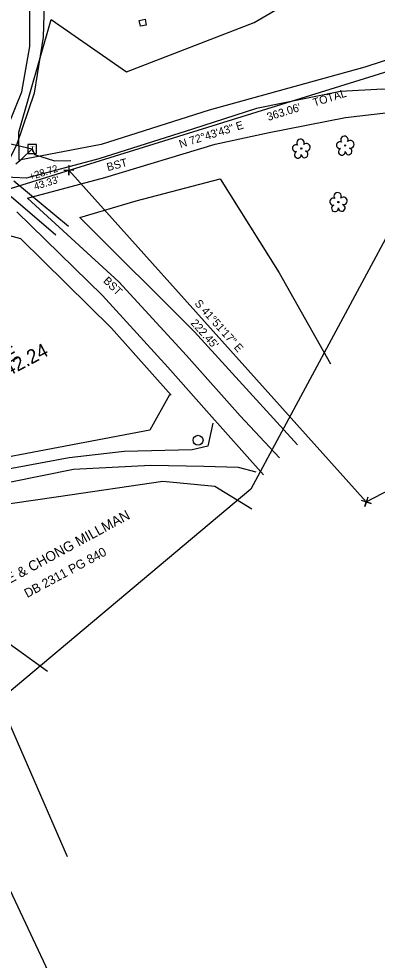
# Model space of a CAD drawing. Extents: x 1380524 to 1382335, y 594765 to 596944.
# Drawn here: x 1381895.1 to 1382074, y 595253.4 to 595723.8 of the extents above; entities that cross this region are included whole.
import ezdxf

# ---------------------------------------------------------------- set-up
doc = ezdxf.new("R2010")
doc.units = 0
for name, color, linetype in [('DTM Contours Major Text', 7, 'Continuous'), ('Exist Horizontal Baseline Alignment Direction Label', 7, 'Continuous'), ('Exist Other Culture Fence Line Text', 7, 'Continuous'), ('Exist Other Culture Well CELL', 7, 'Continuous'), ('Exist Property Tie Line Text', 7, 'Continuous'), ('Exist Right of Way Line', 7, 'Continuous'), ('Exist Roads EOP', 7, 'Continuous'), ('Exist Roads EOP Other', 7, 'Continuous'), ('Exist Structure Major Bridge WW', 7, 'Continuous'), ('Exist Structure Minor Pipes CMP 18 Inch', 7, 'Continuous'), ('Exist Utilities Gas UG Line', 7, 'Continuous'), ('Exist Utilities Power Tower Text', 7, 'Continuous'), ('Exist Utilities Telephone Pedestal CELL', 7, 'Continuous'), ('Exist Utilities Telephone UG Cable', 7, 'Continuous'), ('Prop Drainage Structure Box Number Symbol CELL', 7, 'Continuous'), ('Prop Drainage Structure Pipe Elbow CELL', 7, 'Continuous'), ('Prop Earthen Structure Cut Ditch Special Detail Label', 7, 'Continuous'), ('Prop Erosion Rip Rap At Embankment Detail CELL', 7, 'Continuous'), ('Prop Horizontal Alignment Tick Large', 7, 'Continuous'), ('Scratch_Level_6', 7, 'Continuous')]:
    doc.layers.add(name, color=color, linetype=linetype)

# ---------------------------------------------------------------- blocks, each defined once
blk = doc.blocks.new('EXIST UTILITIES OTHER POLE')
at = {"layer": 'DTM Contours Major Text'}
blk.add_circle((0, 0), 0.0493, dxfattribs=at)
blk = doc.blocks.new('EXIST VEGETATION TREE')
at = {"layer": 'Prop Erosion Rip Rap At Embankment Detail CELL'}
blk.add_line((0, 0), (0, 0), dxfattribs=at)
blk.add_circle((0, 0), 0.00652, dxfattribs=at)
for centre, radius, start, end in [((-0.0077, 0.0575), 0.0371, 330.16508, 219.71335), ((-0.0521, 0.0031), 0.0345, 62.66361, 279.3457), ((0.051, 0.0118), 0.038, 257.1011, 134.19993), ((-0.0341, -0.0624), 0.0338, 111.56708, 6.23104), ((0.0335, -0.058), 0.034, 181.28216, 74.55999)]:
    blk.add_arc(centre, radius, start, end, dxfattribs=at)
blk = doc.blocks.new('EXIST UTILITIES TELEPHONE PEDESTAL')
at = {"layer": 'Exist Utilities Telephone Pedestal CELL'}
blk.add_line((0, 0), (0, 0), dxfattribs=at)
blk.add_lwpolyline([(-0.054, -0.057), (0.057, -0.057), (0.057, 0.055), (-0.054, 0.055), (-0.054, -0.057)], dxfattribs=at)
blk.add_text('T', height=0.0684, dxfattribs=at).set_placement((-0.023, -0.034))

msp = doc.modelspace()

# ---------------------------------------------------------------- linework, layer by layer
at = {"layer": 'Exist Other Culture Well CELL'}
msp.add_lwpolyline([(1381955.16, 595723.01), (1381958.1, 595723.59), (1381958.66, 595720.69), (1381955.73, 595720.12)], close=True, dxfattribs=at)
at = {"layer": 'Exist Roads EOP'}
msp.add_line((1381919.44, 595305.02), (1381827.47, 595515.95), dxfattribs=at)
msp.add_lwpolyline([(1381895.92, 595822.17), (1381902.47, 595793.76), (1381906.2, 595769.7), (1381907.97, 595742.61), (1381907.23, 595714.6), (1381902.73, 595686.65), (1381893.97, 595660.65), (1381884.45, 595642.32), (1381871.1, 595622.85), (1381855.36, 595606.07), (1381838.64, 595592.06), (1381819.68, 595578.62), (1381797.68, 595564.39), (1381777.69, 595551.91), (1381745.42, 595532.92), (1381704.18, 595509.33)], dxfattribs=at)
at = {"layer": 'Exist Roads EOP Other'}
for points in [[(1382105.64, 595686.55), (1382076.86, 595688.73), (1382055.65, 595687.52), (1382013.67, 595678.93), (1381981.76, 595668.62), (1381934.99, 595653.84), (1381898.93, 595644.26), (1381885.04, 595644.78), (1381879.57, 595650.76), (1381878.26, 595659.39)], [(1381899.37, 595634.27), (1381938.06, 595644.53), (1381993.1, 595661.21), (1382020.12, 595666.97), (1382058.22, 595674.5), (1382079.57, 595676.98), (1382102.22, 595669.97)], [(1381899.37, 595634.27), (1381945, 595592.33), (1381978.83, 595555.55), (1382005.63, 595525.4), (1382025.28, 595504.38)], [(1382017.25, 595495.9), (1381988.8, 595527.93), (1381969.42, 595549.67), (1381936.78, 595585.55), (1381894.12, 595627.41)]]:
    msp.add_lwpolyline(points, dxfattribs=at)
at = {"layer": 'Exist Structure Major Bridge WW'}
for p, q in [((1381920.1, 595648.12), (1381920.1, 595648.12)), ((1382068.52, 595482.43), (1382068.52, 595482.43))]:
    msp.add_line(p, q, dxfattribs=at)
for points in [[(1381922.59, 595647.98), (1381917.6, 595648.26), (1381920.1, 595648.12), (1381919.96, 595645.62), (1381920.23, 595650.62)], [(1382069.26, 595484.82), (1382067.79, 595480.04), (1382068.52, 595482.43), (1382070.91, 595481.69), (1382066.13, 595483.17)]]:
    msp.add_lwpolyline(points, dxfattribs=at)
at = {"layer": 'Exist Utilities Gas UG Line'}
msp.add_lwpolyline([(1381819.69, 595439.52), (1382072.96, 594899.37)], dxfattribs=at)
at = {"layer": 'Exist Utilities Power Tower Text'}
for p, q in [((1381879.85, 595635.61), (1382234.24, 595745.79)), ((1381920.1, 595648.12), (1382068.52, 595482.43)), ((1382068.52, 595482.43), (1382333.18, 595622.39))]:
    msp.add_line(p, q, dxfattribs=at)
at = {"layer": 'Exist Utilities Telephone UG Cable'}
for p, q in [((1381900.56, 595709.92), (1381900.64, 595734.04)), ((1381896.64, 595687.3), (1381900.56, 595709.92)), ((1381889.95, 595670.78), (1381896.64, 595687.3)), ((1381888.87, 595661.8), (1381901.65, 595658.8)), ((1381896.49, 595653.89), (1381901.65, 595658.8)), ((1381901.65, 595658.8), (1381902.97, 595656.05)), ((1381902.97, 595656.05), (1381912.82, 595652.88)), ((1381893.52, 595651.3), (1381896.49, 595653.89)), ((1381912.82, 595652.88), (1381920.95, 595652.99)), ((1381919.85, 595620.12), (1381892.51, 595642.73)), ((1381913.61, 595615.68), (1381891.2, 595634.87))]:
    msp.add_line(p, q, dxfattribs=at)
at = {"layer": 'Prop Drainage Structure Box Number Symbol CELL'}
msp.add_lwpolyline([(1382083.62, 595964.41), (1382120.69, 595773.82), (1382095.82, 595646.75), (1382010.85, 595488.75), (1381848.52, 595352.32), (1381617.36, 595239.15), (1381304.92, 595184.07), (1381005.77, 595330.75), (1380937.13, 595525.19), (1380768.47, 595849.39), (1380967, 596250.36)], close=True, dxfattribs=at)
at = {"layer": 'Prop Drainage Structure Pipe Elbow CELL'}
for points in [[(1381991.91, 595521.81), (1381989.38, 595510.26), (1381981.68, 595508.51), (1381947.69, 595507.62), (1381920.27, 595504.37), (1381825.14, 595486.78)], [(1381825.94, 595480.83), (1381875.26, 595489.35), (1381922.43, 595498.8), (1381960.89, 595500.83), (1381987.45, 595500.26), (1382004.5, 595499.71), (1382013.34, 595497.39)]]:
    msp.add_lwpolyline(points, dxfattribs=at)
at = {"layer": 'Prop Earthen Structure Cut Ditch Special Detail Label'}
for points in [[(1382110.04, 595713.45), (1382067.83, 595699.67), (1381990.15, 595678.17), (1381936.17, 595661.06), (1381895.27, 595653.13), (1381895.13, 595667.26), (1381911.22, 595723.52), (1381948.84, 595697.3), (1382012.6, 595721.97), (1382044.15, 595740.68), (1382086.44, 595744.88), (1382118.43, 595781.95)], [(1382034.12, 595510.96), (1381982.79, 595567.38), (1381925.52, 595624.53), (1381953.7, 595632.8), (1381995.62, 595643.94), (1382025.13, 595596.91), (1382050.76, 595551.48)], [(1381970.28, 595535.93), (1381960.54, 595518.19), (1381827.03, 595492.89), (1381805.59, 595553.01), (1381851.27, 595592.48), (1381878.01, 595618.84), (1381895.83, 595614.04), (1381941.37, 595569.31), (1381971.15, 595535.75)], [(1381909.46, 595397.71), (1381844.05, 595444.77), (1381830.9, 595473.02), (1381914.86, 595485.13), (1381966.96, 595492.75), (1381992.9, 595490.3), (1382011.42, 595478.91)]]:
    msp.add_lwpolyline(points, dxfattribs=at)

# ---------------------------------------------------------------- block references
at = {"layer": 'DTM Contours Major Text', "xscale": 50, "yscale": 50}
msp.add_blockref('EXIST UTILITIES OTHER POLE', (1381984.56, 595513.23), dxfattribs=at)
at = {"layer": 'Exist Utilities Telephone Pedestal CELL', "xscale": 40, "yscale": 40}
msp.add_blockref('EXIST UTILITIES TELEPHONE PEDESTAL', (1381901.65, 595658.8), dxfattribs=at)
at = {"layer": 'Prop Erosion Rip Rap At Embankment Detail CELL', "xscale": 50, "yscale": 50}
for p in [(1382036.07, 595659.03), (1382058, 595660.51), (1382054.62, 595632.26)]:
    msp.add_blockref('EXIST VEGETATION TREE', p, dxfattribs=at)

# ---------------------------------------------------------------- texts
at = {"layer": 'Exist Horizontal Baseline Alignment Direction Label'}
msp.add_text('N 61%%d 18\' 37.4" E', height=7, rotation=28.6896, dxfattribs=at).set_placement((1381832.94, 595520.43))
at = {"layer": 'Exist Other Culture Fence Line Text'}
for s, rotation, p in [(' TOTAL', 17.2715, (1382041.18, 595679.48)), ("363.06'", 17.2715, (1382019.65, 595672.79)), ('N 72%%D43\'43" E', 17.2715, (1381975.79, 595659.21)), ('S 41%%D51\'17" E', 311.8548, (1381982.55, 595581.4)), ("222.45'", 311.8548, (1381980.62, 595571.57))]:
    msp.add_text(s, height=4, rotation=rotation, dxfattribs=at).set_placement(p)
at = {"layer": 'Exist Property Tie Line Text'}
for s, p in [('+28.72', (1381900.75, 595643.13)), ("43.33'", (1381903.19, 595638.23))]:
    msp.add_text(s, height=3.6, rotation=17.2715, dxfattribs=at).set_placement(p)
at = {"layer": 'Exist Right of Way Line'}
msp.add_text('CLYDE & CHONG MILLMAN', height=5, rotation=28.4195, dxfattribs=at).set_placement((1381874.6, 595432.85))
at = {"layer": 'Exist Roads EOP Other'}
msp.add_text('BST', height=4, rotation=315.5436, dxfattribs=at).set_placement((1381936.89, 595592.54))
at = {"layer": 'Exist Structure Minor Pipes CMP 18 Inch'}
msp.add_text('DB 2311 PG 840', height=4.5, rotation=28.4195, dxfattribs=at).set_placement((1381899.28, 595434.37))
at = {"layer": 'Prop Horizontal Alignment Tick Large'}
msp.add_text('BST', height=4, rotation=14.851, dxfattribs=at).set_placement((1381939.53, 595647.67))
at = {"layer": 'Scratch_Level_6'}
msp.add_text('-BL- PINC 11+42.24 ', height=7, rotation=27.7977, dxfattribs=at).set_placement((1381835.65, 595516.43))

doc.saveas('drawing.dxf')
